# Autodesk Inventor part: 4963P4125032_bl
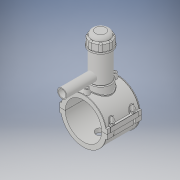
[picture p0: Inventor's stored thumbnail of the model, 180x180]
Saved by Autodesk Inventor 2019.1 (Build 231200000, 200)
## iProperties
Created: 2017-07
Part Number: 4963P4125032_bl
Material: Generic
Document SubType Name: Modeling
Designer: KIM
Density: 1 g/cm^3
Appearance: Default
Author: KIM
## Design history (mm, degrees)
derived "4963P4.ipt"
feature "Solid1::4963P4.ipt" dims "ScaleForDerivedMember" = 10
feature "Solid2::4963P4.ipt" dims "ScaleForDerivedMember" = 10
feature "Solid3::4963P4.ipt" dims "ScaleForDerivedMember" = 10
tag "TaggingFeature1"
body "Solid1"
body "Solid2"
body "Solid3"
other parameters: "d0" = 125 [user parameter], "d2" = 162 [user parameter], "d3" = 31.25 [user parameter], "d4" = 118 [user parameter], "d5" = 0 [user parameter], "d6" = 0.1 [user parameter], "d8" = 0 [user parameter], "d19" = 6 [user parameter], "d20" = 6 [user parameter], "d21" = 70.8 [user parameter], "d23" = 0 [user parameter], "d24" = 35.4 [user parameter], "d26" = 0 [user parameter], "d27" = 3 [user parameter], "d28" = 3 [user parameter], "d29" = 3 [user parameter], "d30" = 41.66667 [user parameter], "d31" = 6 [user parameter], "d32" = 0 [user parameter], "d33" = 0 [user parameter], "d34" = 0.6 [user parameter], "d40" = 79.3 [user parameter], "d41" = 75 [user parameter], "d43" = 0 [user parameter], "d45" = 0 [user parameter], "d47" = 147.05 [user parameter], "d70" = 15 [user parameter], "d72" = 0 [user parameter], "d73" = 6 [user parameter], "d75" = 5 [user parameter], "d76" = 0 [user parameter], "d77" = 6.25 [user parameter], "d78" = 92.5 [user parameter], "d79" = 15 [user parameter], "d80" = 47.2 [user parameter], "d82" = 5 deg [user parameter], "d84" = 4 [user parameter], "d85" = 14 [user parameter], "d86" = 0 [user parameter], "d87" = 3 [user parameter], "d88" = 0 [user parameter], "d89" = 1 [user parameter], "d90" = 1 [user parameter], "d91" = 94.4 [user parameter], "d92" = 0 [user parameter], "d93" = 0.5 [user parameter], "d94" = 65.78947 [user parameter], "d96" = 155.55 [user parameter], "d97" = 2.36 [user parameter], "d98" = 0 [user parameter], "d102" = 1.25 [user parameter], "d120" = 140 deg [user parameter], "d121" = 24.228 [user parameter], "d122" = 20 deg [user parameter], "d123" = 305 [user parameter], "d124" = 91.5 [user parameter], "d126" = 0 [user parameter], "d143" = 128.75 [user parameter], "d145" = 21.15385 [user parameter], "d149" = 1.875 [user parameter], "d150" = 23.26923 [user parameter], "d153" = 118 [user parameter], "d154" = 0 [user parameter], "d156" = 76.25 [user parameter], "d157" = 160 deg [user parameter], "d159" = 5.5 [user parameter], "d161" = 1.875 [user parameter], "d162" = 70.8 [user parameter], "d163" = 0 [user parameter], "d164" = 62.5 [user parameter], "d167" = 12.5 [user parameter], "d168" = 74.39024 [user parameter], "d170" = 3.75 [user parameter], "d172" = 0 [user parameter], "d173" = 1 [user parameter], "d175" = 62.5 [user parameter], "d176" = 20 deg [user parameter], "d177" = 8.75 [user parameter], "d178" = 27.5 [user parameter], "d180" = 0 [user parameter], "d183" = 11 [user parameter], "d184" = 7 [user parameter], "d185" = 38.35 [user parameter], "d186" = 38.35 [user parameter], "d187" = 76.25 [user parameter], "d188" = 8.25 [user parameter], "d189" = 8.75 [user parameter], "d190" = 0 [user parameter], "d191" = 114.375 [user parameter], "d193" = 8 [user parameter], "d194" = 4.13 [user parameter], "d195" = 90 deg [user parameter], "d197" = 0 [user parameter], "d199" = 0 [user parameter], "d200" = 13.75 [user parameter], "d202" = 0 [user parameter], "d203" = 177 [user parameter], "d204" = 71.25 [user parameter], "d205" = 52.5 [user parameter], "d206" = 63.75 [user parameter], "d207" = 132.75 [user parameter], "d208" = 138.06 [user parameter], "d209" = 164.61 [user parameter], "d210" = 64.5 [user parameter], "d211" = 75 [user parameter], "d213" = 36 [user parameter], "d216" = 0 [user parameter], "d217" = 12.5 [user parameter], "d218" = 12.5 [user parameter], "d219" = 2.5 [user parameter], "d222" = 125 [user parameter], "d224" = 0 [user parameter], "d225" = 56 [user parameter], "d226" = 32 [user parameter], "d227" = 25.6 [user parameter], "d228" = 132 [user parameter], "d230" = 5 [user parameter], "d_" = 125 [user parameter], "B_" = 162 [user parameter], "L_" = 118 [user parameter]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
